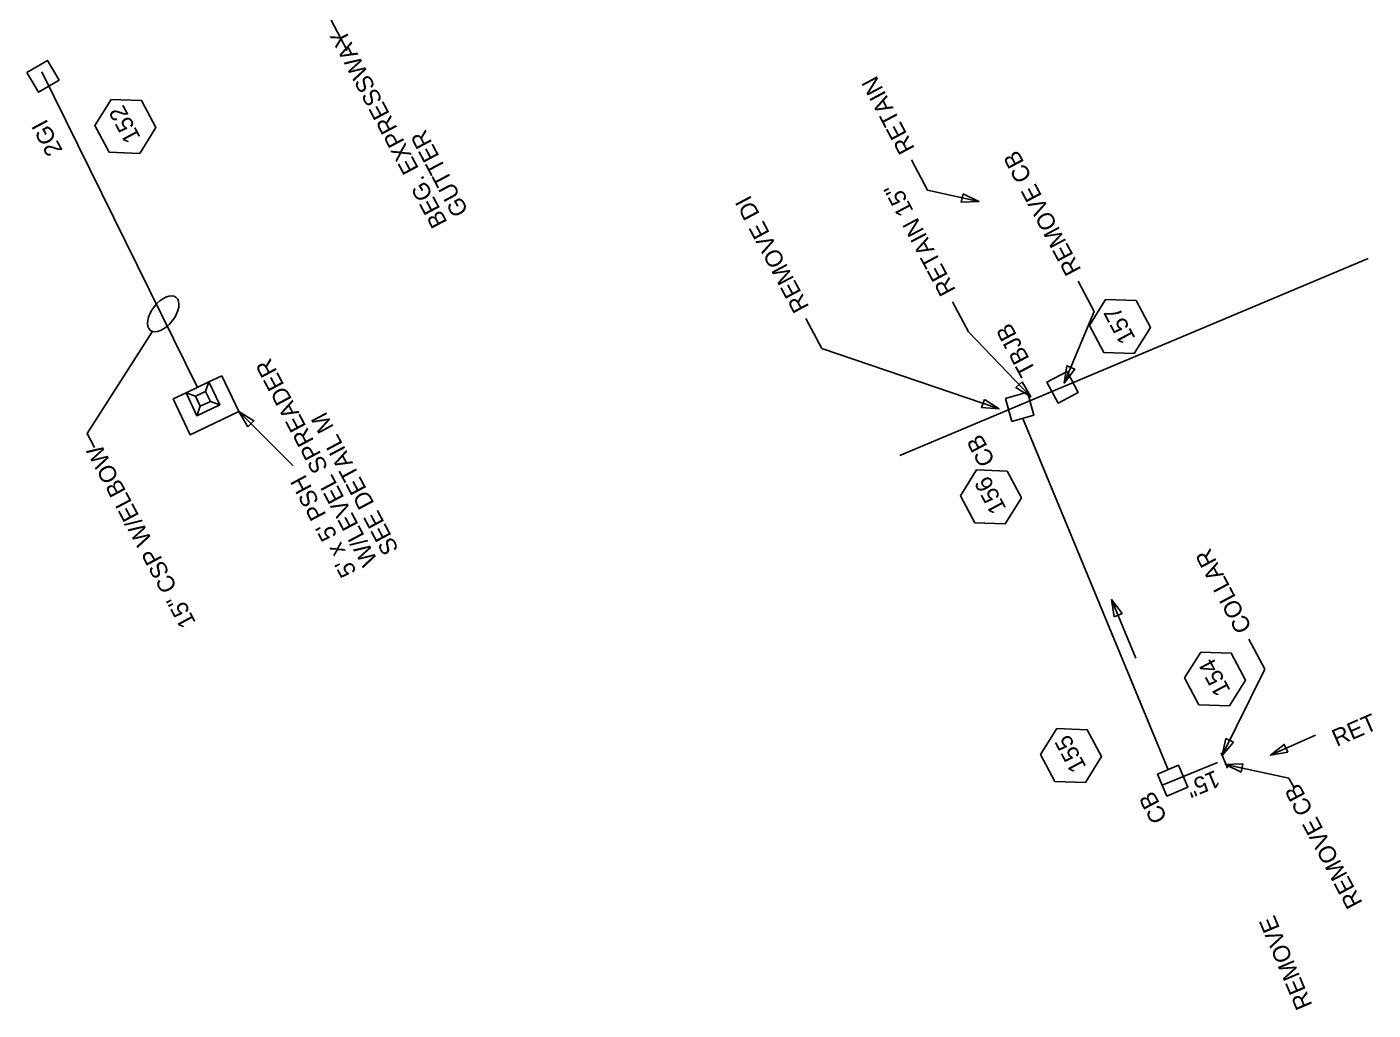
# Model space of a CAD drawing. Extents: x 2384780 to 2405432, y 547869 to 573706.
# Drawn here: x 2402293.1 to 2402688, y 570542 to 570830.5 of the extents above; entities that cross this region are included whole.
import ezdxf

# ---------------------------------------------------------------- set-up
doc = ezdxf.new("R2010")
doc.units = 0
for name, color, linetype in [('Old_Level_1', 7, 'Continuous'), ('Old_Level_10', 7, 'Continuous'), ('Old_Level_20', 7, 'Continuous'), ('Old_Level_5', 7, 'Continuous'), ('Old_Level_63', 7, 'Continuous'), ('Old_Level_9', 7, 'Continuous')]:
    doc.layers.add(name, color=color, linetype=linetype)

# ---------------------------------------------------------------- blocks, each defined once
blk = doc.blocks.new('BUBBLE')
at = {"layer": 'Old_Level_10'}
blk.add_ellipse((0, 0), major_axis=(192, 154), ratio=0.548538, dxfattribs=at)
blk = doc.blocks.new('PSS')
at = {"layer": 'Old_Level_1'}
for p, q in [((0, 14.8595), (0, 31.69675)), ((8.3065, 6.55325), (0, 14.8595)), ((21.4495, 6.591), (29.77475, 14.8595)), ((0, -31.71525), (0.00025, -14.859)), ((8.34375, -6.59075), (0.00025, -14.859)), ((21.46825, -6.55325), (29.77475, -14.8595))]:
    blk.add_line(p, q, dxfattribs=at)
for points in [[(0, 31.69675), (46.6125, 31.69675), (46.61225, -31.71575), (0, -31.71525)], [(0.00025, -14.859), (0, 14.8595)], [(0.00025, -14.859), (29.77475, -14.8595), (29.77475, 14.8595), (0, 14.8595)]]:
    blk.add_lwpolyline(points, dxfattribs=at)
blk.add_lwpolyline([(8.3065, 6.55325), (21.469, 6.553), (21.46825, -6.55325), (8.30625, -6.55325)], close=True, dxfattribs=at)

msp = doc.modelspace()

# ---------------------------------------------------------------- linework, layer by layer
at = {"layer": 'Old_Level_1'}
for p, q in [((2402343.17, 570724.77), (2402297.5, 570817.36)), ((2402552.64, 570791.5), (2402557.33, 570782.67)), ((2402572.36, 570779.28), (2402557.33, 570782.67)), ((2402601.46, 570755.9), (2402606.16, 570747.07)), ((2402564.66, 570749.91), (2402569.35, 570741.08)), ((2402521.64, 570744.99), (2402526.34, 570736.16)), ((2402597.42, 570726.01), (2402606.16, 570747.07)), ((2402587.58, 570721.95), (2402569.35, 570741.08)), ((2402578.31, 570718.42), (2402526.34, 570736.16)), ((2402627.85, 570612.57), (2402585.28, 570715.66)), ((2402611.31, 570662.5), (2402618.41, 570645.34)), ((2402645.29, 570612.97), (2402643.4, 570617.53)), ((2402642.39, 570614.68), (2402626.12, 570608.03))]:
    msp.add_line(p, q, dxfattribs=at)
for points in [[(2402567.76, 570781.6), (2402572.36, 570779.28), (2402567.21, 570779.16)], [(2402600.49, 570730.15), (2402597.42, 570726.01), (2402598.18, 570731.1)], [(2402585.03, 570726.43), (2402587.58, 570721.95), (2402583.22, 570724.71)], [(2402573.98, 570721.22), (2402578.31, 570718.42), (2402573.17, 570718.85)], [(2402582.05, 570714.76), (2402580.18, 570721.53), (2402586.65, 570723.32), (2402588.51, 570716.56)], [(2402612.07, 570657.4), (2402611.31, 570662.5), (2402614.37, 570658.36)], [(2402627.48, 570604.79), (2402624.76, 570611.27), (2402630.94, 570613.87), (2402633.65, 570607.41)]]:
    msp.add_lwpolyline(points, close=True, dxfattribs=at)
msp.add_lwpolyline([(2402329.9, 570741.08), (2402310.79, 570711.21), (2402312.99, 570707.08)], dxfattribs=at)
at = {"layer": 'Old_Level_20'}
for points in [[(2402317.85, 570809.24), (2402313.11, 570801.65), (2402317.31, 570793.75), (2402326.26, 570793.44), (2402331, 570801.03), (2402326.8, 570808.93)], [(2402609.54, 570750.52), (2402604.8, 570742.93), (2402609, 570735.03), (2402617.95, 570734.72), (2402622.69, 570742.3), (2402618.49, 570750.21)], [(2402571.69, 570700.53), (2402566.94, 570692.94), (2402571.15, 570685.04), (2402580.09, 570684.73), (2402584.83, 570692.32), (2402580.63, 570700.22)], [(2402637.46, 570647.09), (2402632.72, 570639.51), (2402636.92, 570631.6), (2402645.86, 570631.29), (2402650.6, 570638.88), (2402646.4, 570646.78)], [(2402595.2, 570624.62), (2402590.46, 570617.03), (2402594.66, 570609.13), (2402603.61, 570608.82), (2402608.35, 570616.41), (2402604.15, 570624.31)]]:
    msp.add_lwpolyline(points, close=True, dxfattribs=at)
at = {"layer": 'Old_Level_5'}
for p, q in [((2402387.04, 570823.66), (2402382.35, 570832.49)), ((2402355.34, 570717.66), (2402371.2, 570701.71)), ((2402651.53, 570650.88), (2402656.23, 570642.05)), ((2402643.74, 570616.72), (2402656.23, 570642.05)), ((2402657.88, 570616.8), (2402671.1, 570622.7)), ((2402644.66, 570614.09), (2402663.28, 570610.1)), ((2402663.28, 570610.1), (2402664.91, 570607.02))]:
    msp.add_line(p, q, dxfattribs=at)
for points in [[(2402357.98, 570713.23), (2402355.34, 570717.66), (2402359.75, 570714.99)], [(2402647.07, 570620.65), (2402643.74, 570616.72), (2402644.83, 570621.76)], [(2402662.96, 570617.7), (2402657.88, 570616.8), (2402661.94, 570619.98)], [(2402649.28, 570611.82), (2402644.66, 570614.09), (2402649.81, 570614.26)]]:
    msp.add_lwpolyline(points, close=True, dxfattribs=at)
at = {"layer": 'Old_Level_63'}
msp.add_line((2402549.23, 570704.77), (2402686.53, 570762.6), dxfattribs=at)
at = {"layer": 'Old_Level_9'}
for points in [[(2402293.15, 570817.15), (2402299.21, 570820.71), (2402302.6, 570814.92), (2402296.55, 570811.38)], [(2402595.59, 570720.11), (2402592.29, 570726.31), (2402598.22, 570729.46), (2402601.5, 570723.27)]]:
    msp.add_lwpolyline(points, close=True, dxfattribs=at)

# ---------------------------------------------------------------- block references
at = {"layer": 'Old_Level_5'}
for name, p, xscale, yscale, rotation in [('BUBBLE', (2402333.13, 570746.33), 0.025000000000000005, 0.025000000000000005, -166.63557136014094), ('PSS', (2402343.17, 570724.77), 0.2499999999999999, -0.24999999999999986, -64.5192917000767)]:
    msp.add_blockref(name, p, dxfattribs=dict(at, xscale=xscale, yscale=yscale, rotation=rotation))

# ---------------------------------------------------------------- texts
at = {"layer": 'Old_Level_1'}
for s, rotation, p in [('RETAIN', 117.9999, (2402553.67, 570794.88)), ('REMOVE CB', 117.9999, (2402602.5, 570759.28)), ('RETAIN 15"', 117.9999, (2402565.69, 570753.29)), ('REMOVE DI', 117.9999, (2402522.68, 570748.37)), ('TBJB', 117.9999, (2402589.21, 570729.59)), ('CB', 117.9999, (2402577.26, 570703.2)), ('15"', 202.2263, (2402641.73, 570612.52)), ('CB', 117.9999, (2402627.79, 570598.44)), ('REMOVE', 112.8772, (2402670.27, 570543.45))]:
    msp.add_text(s, height=5, rotation=rotation, dxfattribs=at).set_placement(p)
at = {"layer": 'Old_Level_20'}
for s, p in [('152', (2402326.61, 570798.11)), ('157', (2402618.4, 570739.19)), ('156', (2402580.51, 570689.27)), ('154', (2402646.29, 570635.82)), ('155', (2402604.01, 570613.38))]:
    msp.add_text(s, height=5, rotation=117.9999, dxfattribs=at).set_placement(p)
at = {"layer": 'Old_Level_5'}
for s, rotation, p in [('BEG. EXPRESSWAY', 118, (2402416.59, 570773.22)), ('2GI', 117.9999, (2402303.74, 570794.32)), ('GUTTER', 118, (2402422.77, 570776.51)), ('W/LEVEL SPREADER', 117.9999, (2402396.13, 570673.97)), ('SEE DETAIL M', 117.9999, (2402402.31, 570677.25)), ('15" CSP W/ELBOW', 117.9999, (2402342.82, 570655.79)), ("5' x 5' PSH ", 117.9999, (2402389.95, 570670.68)), ('COLLAR', 117.9999, (2402652.57, 570654.27)), ('RET', 23.5675, (2402677.32, 570619.26)), ('REMOVE CB', 117.9999, (2402685.02, 570573.49))]:
    msp.add_text(s, height=5, rotation=rotation, dxfattribs=at).set_placement(p)

doc.saveas('drawing.dxf')
